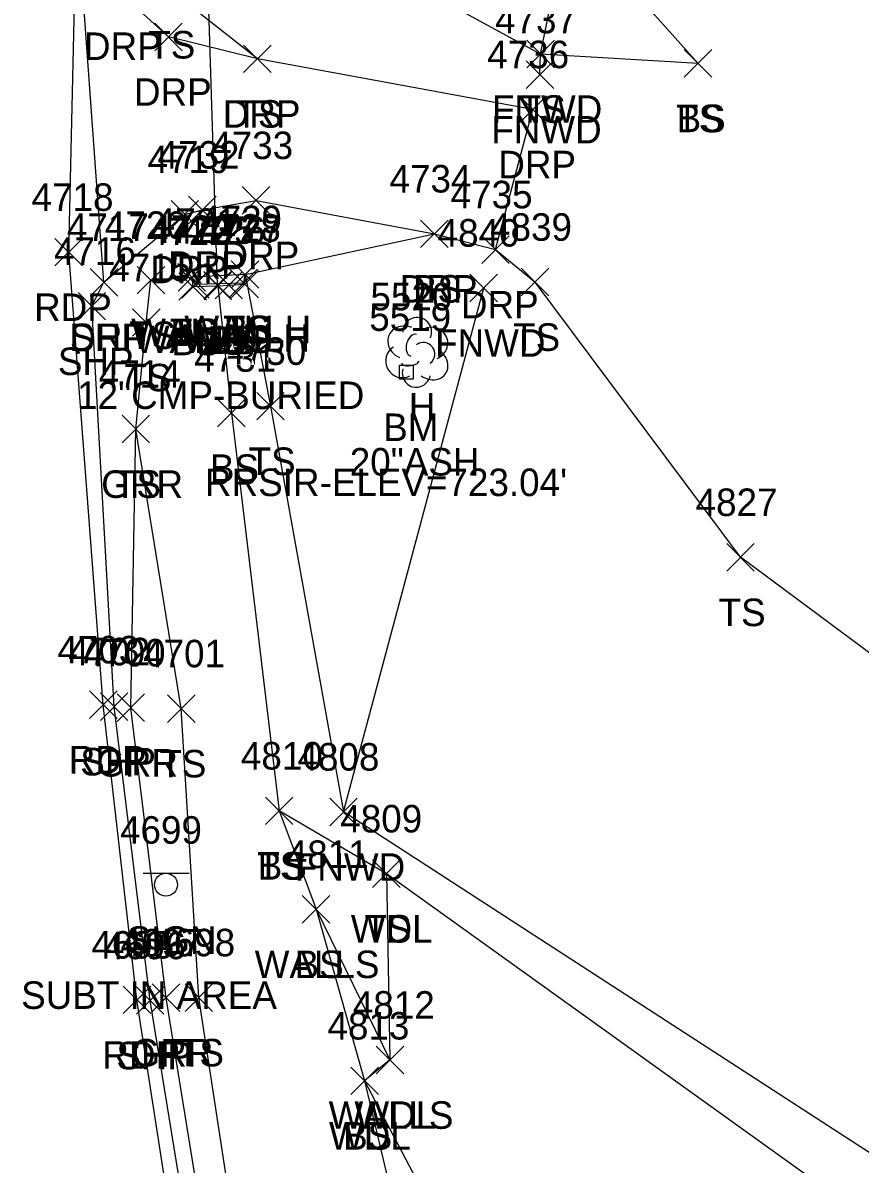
# Model space of a CAD drawing. Extents: x 1601151 to 1602912, y 499508 to 501770.
# Drawn here: x 1601465.9 to 1601526.7, y 501166.3 to 501249.2 of the extents above; entities that cross this region are included whole.
import ezdxf

# ---------------------------------------------------------------- set-up
doc = ezdxf.new("R2010")
doc.units = 0
for name, color, linetype in [('C_A', 7, 'Continuous'), ('C_C', 7, 'Continuous'), ('C_I', 7, 'Continuous'), ('CPBM', 7, 'Continuous'), ('D_A', 7, 'Continuous'), ('D_C', 7, 'Continuous'), ('D_I', 7, 'Continuous'), ('D_TIC', 7, 'Continuous'), ('DCP', 7, 'Continuous'), ('DHW', 7, 'Continuous'), ('L_A', 7, 'Continuous'), ('L_C', 7, 'Continuous'), ('L_I', 7, 'Continuous'), ('L_TIC', 7, 'Continuous'), ('LAWA', 7, 'Continuous'), ('LELB', 7, 'Continuous'), ('LFNC', 7, 'Continuous'), ('LTD', 7, 'Continuous'), ('LWS', 7, 'Continuous'), ('P_A', 7, 'Continuous'), ('P_I', 7, 'Continuous'), ('P_TIC', 7, 'Continuous'), ('PET', 7, 'Continuous'), ('PSP', 7, 'Continuous'), ('R_A', 7, 'Continuous'), ('R_I', 7, 'Continuous'), ('R_TIC', 7, 'Continuous'), ('RDP', 7, 'Continuous'), ('RGR', 7, 'Continuous'), ('S_A', 7, 'Continuous'), ('S_C', 7, 'Continuous'), ('S_I', 7, 'Continuous'), ('SSGN', 7, 'Continuous')]:
    doc.layers.add(name, color=color, linetype=linetype)

msp = doc.modelspace()

# ---------------------------------------------------------------- linework, layer by layer
at = {"layer": 'CPBM'}
for p, q in [((1601493.23, 501223.31), (1601493.23, 501224.31)), ((1601493.23, 501224.31), (1601494.23, 501224.31)), ((1601493.733, 501223.811), (1601493.733, 501223.811)), ((1601493.733, 501223.811), (1601493.733, 501223.811)), ((1601494.23, 501224.31), (1601494.23, 501223.31)), ((1601494.23, 501223.31), (1601493.23, 501223.31))]:
    msp.add_line(p, q, dxfattribs=at)
at = {"layer": 'D_TIC'}
for points in [[(1601481.012, 501229.91), (1601483.012, 501231.91)], [(1601483.012, 501229.91), (1601481.012, 501231.91)], [(1601477.146, 501229.707), (1601479.146, 501231.707)], [(1601479.146, 501229.707), (1601477.146, 501231.707)], [(1601477.41, 501229.196), (1601479.41, 501231.196)], [(1601479.41, 501229.196), (1601477.41, 501231.196)], [(1601479.011, 501229.137), (1601481.011, 501231.137)], [(1601481.011, 501229.137), (1601479.011, 501231.137)], [(1601480.918, 501229.293), (1601482.918, 501231.293)], [(1601482.918, 501229.293), (1601480.918, 501231.293)]]:
    msp.add_lwpolyline(points, dxfattribs=at)
at = {"layer": 'DCP'}
msp.add_lwpolyline([(1601480.011, 501230.137), (1601479.12, 501258.606)], dxfattribs=at)
at = {"layer": 'DHW'}
msp.add_lwpolyline([(1601478.146, 501230.707), (1601478.41, 501230.196), (1601481.918, 501230.293), (1601482.012, 501230.91), (1601478.146, 501230.707)], dxfattribs=at)
at = {"layer": 'L_TIC'}
for points in [[(1601502.48, 501245.927), (1601504.48, 501247.927)], [(1601504.48, 501245.927), (1601502.48, 501247.927)], [(1601502.48, 501245.927), (1601504.48, 501247.927)], [(1601504.48, 501245.927), (1601502.48, 501247.927)], [(1601481.904, 501245.572), (1601483.904, 501247.572)], [(1601483.904, 501245.572), (1601481.904, 501247.572)], [(1601513.919, 501245.246), (1601515.919, 501247.246)], [(1601515.919, 501245.246), (1601513.919, 501247.246)], [(1601513.919, 501245.246), (1601515.919, 501247.246)], [(1601515.919, 501245.246), (1601513.919, 501247.246)], [(1601502.433, 501244.429), (1601504.433, 501246.429)], [(1601504.433, 501244.429), (1601502.433, 501246.429)], [(1601494.765, 501232.865), (1601496.765, 501234.865)], [(1601496.765, 501232.865), (1601494.765, 501234.865)], [(1601481.012, 501229.91), (1601483.012, 501231.91)], [(1601483.012, 501229.91), (1601481.012, 501231.91)], [(1601481.012, 501229.91), (1601483.012, 501231.91)], [(1601483.012, 501229.91), (1601481.012, 501231.91)], [(1601474.177, 501229.496), (1601476.177, 501231.496)], [(1601476.177, 501229.496), (1601474.177, 501231.496)], [(1601477.146, 501229.707), (1601479.146, 501231.707)], [(1601479.146, 501229.707), (1601477.146, 501231.707)], [(1601477.146, 501229.707), (1601479.146, 501231.707)], [(1601479.146, 501229.707), (1601477.146, 501231.707)], [(1601479.037, 501229.075), (1601481.037, 501231.075)], [(1601481.037, 501229.075), (1601479.037, 501231.075)], [(1601479.037, 501229.075), (1601481.037, 501231.075)], [(1601481.037, 501229.075), (1601479.037, 501231.075)], [(1601479.837, 501229.133), (1601481.837, 501231.133)], [(1601481.837, 501229.133), (1601479.837, 501231.133)], [(1601480.999, 501229.207), (1601482.999, 501231.207)], [(1601482.999, 501229.207), (1601480.999, 501231.207)], [(1601502.076, 501229.359), (1601504.076, 501231.359)], [(1601504.076, 501229.359), (1601502.076, 501231.359)], [(1601477.207, 501229.04), (1601479.207, 501231.04)], [(1601479.207, 501229.04), (1601477.207, 501231.04)], [(1601498.348, 501228.934), (1601500.348, 501230.934)], [(1601500.348, 501228.934), (1601498.348, 501230.934)], [(1601473.84, 501226.419), (1601475.84, 501228.419)], [(1601475.84, 501226.419), (1601473.84, 501228.419)], [(1601482.857, 501220.341), (1601484.857, 501222.341)], [(1601484.857, 501220.341), (1601482.857, 501222.341)], [(1601480.019, 501219.841), (1601482.019, 501221.841)], [(1601482.019, 501219.841), (1601480.019, 501221.841)], [(1601473.075, 501218.68), (1601475.075, 501220.68)], [(1601475.075, 501218.68), (1601473.075, 501220.68)], [(1601516.999, 501209.362), (1601518.999, 501211.362)], [(1601518.999, 501209.362), (1601516.999, 501211.362)], [(1601476.376, 501198.371), (1601478.376, 501200.371)], [(1601478.376, 501198.371), (1601476.376, 501200.371)], [(1601483.49, 501190.946), (1601485.49, 501192.946)], [(1601485.49, 501190.946), (1601483.49, 501192.946)], [(1601483.49, 501190.946), (1601485.49, 501192.946)], [(1601485.49, 501190.946), (1601483.49, 501192.946)], [(1601488.16, 501190.866), (1601490.16, 501192.866)], [(1601490.16, 501190.866), (1601488.16, 501192.866)], [(1601491.276, 501186.375), (1601493.276, 501188.375)], [(1601493.276, 501186.375), (1601491.276, 501188.375)], [(1601491.276, 501186.375), (1601493.276, 501188.375)], [(1601493.276, 501186.375), (1601491.276, 501188.375)], [(1601486.168, 501183.794), (1601488.168, 501185.794)], [(1601488.168, 501183.794), (1601486.168, 501185.794)], [(1601486.168, 501183.794), (1601488.168, 501185.794)], [(1601488.168, 501183.794), (1601486.168, 501185.794)], [(1601477.65, 501177.376), (1601479.65, 501179.376)], [(1601479.65, 501177.376), (1601477.65, 501179.376)], [(1601491.537, 501172.845), (1601493.537, 501174.845)], [(1601493.537, 501172.845), (1601491.537, 501174.845)], [(1601491.537, 501172.845), (1601493.537, 501174.845)], [(1601493.537, 501172.845), (1601491.537, 501174.845)], [(1601489.694, 501171.332), (1601491.694, 501173.332)], [(1601491.694, 501171.332), (1601489.694, 501173.332)], [(1601489.694, 501171.332), (1601491.694, 501173.332)], [(1601491.694, 501171.332), (1601489.694, 501173.332)]]:
    msp.add_lwpolyline(points, dxfattribs=at)
at = {"layer": 'LAWA'}
msp.add_lwpolyline([(1601618.164, 501105.861), (1601588.542, 501115.646), (1601565.4, 501138.093), (1601542.306, 501150.134), (1601528.872, 501161.109), (1601492.276, 501187.375), (1601492.537, 501173.845), (1601490.694, 501172.332), (1601496.325, 501148.536)], dxfattribs=at)
at = {"layer": 'LELB'}
for points in [[(1601514.919, 501246.246), (1601505.474, 501256.797), (1601486.015, 501263.271), (1601485.756, 501300.208), (1601487.942, 501339.809), (1601496.982, 501373.173)], [(1601482.904, 501246.572), (1601476.571, 501251.598), (1601473.853, 501259.286)], [(1601514.919, 501246.246), (1601503.48, 501246.927), (1601485.983, 501256.464), (1601481.191, 501258.282)], [(1601478.146, 501230.707), (1601478.207, 501230.04), (1601480.037, 501230.075), (1601480.837, 501230.133), (1601481.999, 501230.207), (1601482.012, 501230.91), (1601495.765, 501233.865)], [(1601500.206, 501232.716), (1601503.076, 501230.359)], [(1601550.273, 500878.876), (1601544.145, 500896.684), (1601533.206, 500944.653), (1601522.547, 500986.897), (1601510.781, 501028.923), (1601500.628, 501071.758), (1601491.578, 501108.108), (1601483.828, 501144.538), (1601478.65, 501178.376), (1601477.376, 501199.371), (1601474.075, 501219.68), (1601474.84, 501227.419), (1601475.177, 501230.496), (1601478.146, 501230.707)], [(1601482.012, 501230.91), (1601483.857, 501221.341)], [(1601639.017, 501157.644), (1601611.095, 501171.108), (1601584.804, 501178.755), (1601542.463, 501192.221), (1601517.999, 501210.362), (1601503.076, 501230.359)], [(1601480.037, 501230.075), (1601481.019, 501220.841), (1601484.49, 501191.946), (1601487.168, 501184.794), (1601490.694, 501172.332), (1601502.321, 501150.223), (1601523.309, 501131.225), (1601544.426, 501107.876), (1601586.902, 501067.79), (1601615.046, 501058.933)], [(1601483.857, 501221.341), (1601489.16, 501191.866)], [(1601492.276, 501187.375), (1601484.49, 501191.946)]]:
    msp.add_lwpolyline(points, dxfattribs=at)
at = {"layer": 'LFNC'}
for points in [[(1601503.433, 501245.429), (1601503.48, 501246.927), (1601505.474, 501256.797), (1601514.287, 501293.696), (1601516.13, 501305.057)], [(1601618.917, 501107.15), (1601588.692, 501127.511), (1601566.226, 501142.234), (1601531.272, 501164.593), (1601489.16, 501191.866), (1601499.348, 501229.934)]]:
    msp.add_lwpolyline(points, dxfattribs=at)
at = {"layer": 'LTD'}
msp.add_line((1601494.469, 501225.304), (1601494.469, 501225.304), dxfattribs=at)
msp.add_line((1601494.469, 501225.304), (1601494.469, 501225.304), dxfattribs=at)
msp.add_arc((1601494.515, 501226.738), 1.047, 335.52715, 180.95627, dxfattribs=at)
for centre, major_axis, ratio, start_param, end_param in [((1601493.677, 501225.97), (1.21, -0.512), 0.895232, 1.570796, 4.712389), ((1601495.51, 501225.887), (-1.141, -0.483), 0.949671, 1.570796, 4.712389), ((1601494.26, 501225.762), (-0.208, -0.792), 0.645439, 3.141593, 6.283185), ((1601493.385, 501224.595), (0.584, -1.042), 0.959034, 3.141593, 6.283185), ((1601494.969, 501225.137), (-0.5, 0.667), 0.989748, 3.141593, 6.283185), ((1601495.469, 501224.47), (-1.09, 0.792), 0.841452, 1.570796, 4.712389), ((1601494.01, 501224.554), (-0.625, -0.083), 0.423636, 0, 3.141593), ((1601494.469, 501223.804), (0.265, 1.061), 0.942809, 1.570796, 4.712389)]:
    msp.add_ellipse(centre, major_axis=major_axis, ratio=ratio, start_param=start_param, end_param=end_param, dxfattribs=at)
at = {"layer": 'LWS'}
msp.add_lwpolyline([(1601487.168, 501184.794), (1601492.537, 501173.845)], dxfattribs=at)
at = {"layer": 'P_TIC'}
for points in [[(1601468.2, 501231.531), (1601470.2, 501233.531)], [(1601470.2, 501231.531), (1601468.2, 501233.531)], [(1601470.762, 501229.344), (1601472.762, 501231.344)], [(1601472.762, 501229.344), (1601470.762, 501231.344)], [(1601469.881, 501227.604), (1601471.881, 501229.604)], [(1601471.881, 501227.604), (1601469.881, 501229.604)], [(1601470.716, 501198.657), (1601472.716, 501200.657)], [(1601472.716, 501198.657), (1601470.716, 501200.657)], [(1601471.506, 501198.517), (1601473.506, 501200.517)], [(1601473.506, 501198.517), (1601471.506, 501200.517)], [(1601473.157, 501177.212), (1601475.157, 501179.212)], [(1601475.157, 501177.212), (1601473.157, 501179.212)], [(1601474.123, 501177.167), (1601476.123, 501179.167)], [(1601476.123, 501177.167), (1601474.123, 501179.167)]]:
    msp.add_lwpolyline(points, dxfattribs=at)
at = {"layer": 'PET'}
msp.add_lwpolyline([(1601544.222, 500876.259), (1601539.18, 500895.586), (1601526.946, 500943.367), (1601516.322, 500985.835), (1601505.443, 501027.918), (1601495.097, 501070.934), (1601486.999, 501107.137), (1601479.481, 501143.907), (1601474.157, 501178.212), (1601471.716, 501199.657), (1601469.2, 501232.531), (1601470.852, 501304.368), (1601475.757, 501342.264), (1601481.23, 501372.738), (1601489.711, 501419.604), (1601498.833, 501463.236), (1601509.832, 501514.715), (1601518.287, 501552.564), (1601529.192, 501602.718), (1601530.089, 501606.928), (1601533.566, 501622.361), (1601544.656, 501669.882)], dxfattribs=at)
at = {"layer": 'PSP'}
msp.add_lwpolyline([(1601528.905, 500943.602), (1601517.981, 500986.134), (1601507.436, 501028.318), (1601496.624, 501071.208), (1601488.243, 501107.282), (1601480.675, 501144.124), (1601475.123, 501178.167), (1601472.506, 501199.517), (1601470.881, 501228.604), (1601471.762, 501230.344), (1601469.82, 501257.161), (1601471.596, 501304.231), (1601477.349, 501341.751), (1601482.297, 501372.174), (1601491.335, 501419.441), (1601500.561, 501462.845), (1601511.149, 501514.361), (1601520.065, 501552.198), (1601531.25, 501603.068), (1601534.571, 501619.483), (1601535.229, 501620.043), (1601536.149, 501623.424), (1601535.022, 501624.102), (1601546.219, 501669.664)], dxfattribs=at)
at = {"layer": 'R_TIC'}
for points in [[(1601475.453, 501247.166), (1601477.453, 501249.166)], [(1601477.453, 501247.166), (1601475.453, 501249.166)], [(1601481.904, 501245.572), (1601483.904, 501247.572)], [(1601483.904, 501245.572), (1601481.904, 501247.572)], [(1601501.918, 501241.897), (1601503.918, 501243.897)], [(1601503.918, 501241.897), (1601501.918, 501243.897)], [(1601481.813, 501235.293), (1601483.813, 501237.293)], [(1601483.813, 501235.293), (1601481.813, 501237.293)], [(1601476.633, 501234.273), (1601478.633, 501236.273)], [(1601478.633, 501234.273), (1601476.633, 501236.273)], [(1601477.914, 501234.599), (1601479.914, 501236.599)], [(1601479.914, 501234.599), (1601477.914, 501236.599)], [(1601494.765, 501232.865), (1601496.765, 501234.865)], [(1601496.765, 501232.865), (1601494.765, 501234.865)], [(1601499.206, 501231.716), (1601501.206, 501233.716)], [(1601501.206, 501231.716), (1601499.206, 501233.716)], [(1601470.762, 501229.344), (1601472.762, 501231.344)], [(1601472.762, 501229.344), (1601470.762, 501231.344)], [(1601473.075, 501218.68), (1601475.075, 501220.68)], [(1601475.075, 501218.68), (1601473.075, 501220.68)], [(1601472.71, 501198.437), (1601474.71, 501200.437)], [(1601474.71, 501198.437), (1601472.71, 501200.437)], [(1601475.276, 501177.369), (1601477.276, 501179.369)], [(1601477.276, 501177.369), (1601475.276, 501179.369)]]:
    msp.add_lwpolyline(points, dxfattribs=at)
at = {"layer": 'RDP'}
msp.add_lwpolyline([(1601471.762, 501230.344), (1601477.633, 501235.273), (1601478.914, 501235.599), (1601482.813, 501236.293), (1601495.765, 501233.865), (1601500.206, 501232.716), (1601502.918, 501242.897), (1601482.904, 501246.572), (1601476.453, 501248.166), (1601472.823, 501251.493), (1601469.82, 501257.161)], dxfattribs=at)
at = {"layer": 'RGR'}
msp.add_lwpolyline([(1601542.078, 500896.217), (1601529.827, 500944.353), (1601519.229, 500986.393), (1601508.51, 501028.956), (1601497.809, 501071.106), (1601488.919, 501107.458), (1601481.799, 501144.254), (1601476.276, 501178.369), (1601473.71, 501199.437), (1601474.075, 501219.68)], dxfattribs=at)
at = {"layer": 'SSGN'}
for p, q in [((1601474.616, 501187.41), (1601477.95, 501187.41)), ((1601476.263, 501186.577), (1601476.263, 501186.577))]:
    msp.add_line(p, q, dxfattribs=at)
msp.add_circle((1601476.263, 501186.577), 0.833, dxfattribs=at)

# ---------------------------------------------------------------- texts
at = {"layer": 'C_A'}
msp.add_text('BM', height=2, dxfattribs=at).set_placement((1601492.048, 501218.811))
at = {"layer": 'C_C'}
msp.add_text("RRSIR-ELEV=723.04'", height=2, dxfattribs=at).set_placement((1601479.103, 501214.811))
at = {"layer": 'C_I'}
msp.add_text('5519', height=2, dxfattribs=at).set_placement((1601491.032, 501226.811))
at = {"layer": 'D_A'}
for s, p in [('WALLH', (1601477.603, 501225.91)), ('WALLH', (1601473.737, 501225.707)), ('WALLH', (1601474, 501225.196)), ('WALLH', (1601477.508, 501225.293)), ('P', (1601479.389, 501225.137))]:
    msp.add_text(s, height=2, dxfattribs=at).set_placement(p)
at = {"layer": 'D_C'}
msp.add_text('12"CMP-BURIED', height=2, dxfattribs=at).set_placement((1601469.814, 501221.137))
at = {"layer": 'D_I'}
for s, p in [('4723', (1601475.15, 501233.196)), ('4721', (1601475.453, 501233.707)), ('4728', (1601478.658, 501233.293)), ('4729', (1601478.744, 501233.91)), ('4725', (1601476.751, 501233.137))]:
    msp.add_text(s, height=2, dxfattribs=at).set_placement(p)
at = {"layer": 'L_A'}
for s, p in [('TS', (1601474.98, 501246.598)), ('TS', (1601481.314, 501241.572)), ('FNWD', (1601499.944, 501241.927)), ('TS', (1601501.889, 501241.927)), ('TS', (1601513.328, 501241.246)), ('BS', (1601513.359, 501241.246)), ('FNWD', (1601499.897, 501240.429)), ('BS', (1601494.206, 501228.865)), ('TS', (1601480.421, 501225.91)), ('BS', (1601480.453, 501225.91)), ('TS', (1601473.586, 501225.496)), ('TS', (1601476.556, 501225.707)), ('BS', (1601476.587, 501225.707)), ('BS', (1601476.648, 501225.04)), ('BS', (1601478.478, 501225.075)), ('BS', (1601478.478, 501225.075)), ('BS', (1601479.278, 501225.133)), ('BS', (1601480.44, 501225.207)), ('FNWD', (1601495.813, 501224.934)), ('TS', (1601501.486, 501225.359)), ('TS', (1601473.249, 501222.419)), ('H', (1601493.902, 501220.304)), ('BS', (1601479.46, 501215.841)), ('TS', (1601482.266, 501216.341)), ('TS', (1601472.485, 501214.68)), ('TS', (1601516.409, 501205.362)), ('TS', (1601475.786, 501194.371)), ('TS', (1601482.899, 501186.946)), ('BS', (1601482.931, 501186.946)), ('FNWD', (1601485.625, 501186.866)), ('WDL', (1601489.693, 501182.375)), ('TS', (1601490.685, 501182.375)), ('WALLS', (1601482.711, 501179.794)), ('BS', (1601485.609, 501179.794)), ('TS', (1601477.059, 501173.376)), ('WALLS', (1601488.08, 501168.845)), ('WDL', (1601489.954, 501168.845)), ('WDL', (1601488.111, 501167.332)), ('BS', (1601489.135, 501167.332))]:
    msp.add_text(s, height=2, dxfattribs=at).set_placement(p)
at = {"layer": 'L_C'}
msp.add_text('20"ASH', height=2, dxfattribs=at).set_placement((1601489.618, 501216.304))
at = {"layer": 'L_I'}
for s, p in [('4737', (1601500.173, 501248.429)), ('4734', (1601492.505, 501236.865)), ('4720', (1601471.83, 501233.496)), ('4721', (1601475.453, 501233.707)), ('4721', (1601475.453, 501233.707)), ('4727', (1601478.739, 501233.207)), ('4729', (1601478.744, 501233.91)), ('4729', (1601478.744, 501233.91)), ('4839', (1601499.809, 501233.359)), ('4722', (1601474.948, 501233.04)), ('4724', (1601476.777, 501233.075)), ('4724', (1601476.777, 501233.075)), ('4726', (1601477.522, 501233.133)), ('4840', (1601496.002, 501232.934)), ('4715', (1601472.147, 501230.419)), ('5520', (1601491.122, 501228.304)), ('4730', (1601480.51, 501224.341)), ('4731', (1601478.326, 501223.841)), ('4714', (1601471.383, 501222.68)), ('4827', (1601514.74, 501213.362)), ('4701', (1601474.605, 501202.371)), ('4810', (1601481.71, 501194.946)), ('4810', (1601481.71, 501194.946)), ('4808', (1601485.822, 501194.866)), ('4809', (1601488.929, 501190.375)), ('4809', (1601488.929, 501190.375)), ('4811', (1601485.042, 501187.794)), ('4811', (1601485.042, 501187.794)), ('4698', (1601475.343, 501181.376)), ('4812', (1601489.844, 501176.845)), ('4812', (1601489.844, 501176.845)), ('4813', (1601488.001, 501175.332)), ('4813', (1601488.001, 501175.332))]:
    msp.add_text(s, height=2, dxfattribs=at).set_placement(p)
at = {"layer": 'P_A'}
for s, p in [('RDP', (1601466.688, 501227.531)), ('SHP', (1601469.298, 501225.344)), ('SHP', (1601468.416, 501223.604)), ('RDP', (1601469.204, 501194.657)), ('SHP', (1601470.041, 501194.517)), ('RDP', (1601471.646, 501173.212)), ('SHP', (1601472.659, 501173.167))]:
    msp.add_text(s, height=2, dxfattribs=at).set_placement(p)
at = {"layer": 'P_I'}
for s, p in [('4718', (1601466.507, 501235.531)), ('4717', (1601469.07, 501233.344)), ('4716', (1601468.133, 501231.604)), ('4703', (1601468.378, 501202.657)), ('4702', (1601469.167, 501202.517)), ('4695', (1601470.85, 501181.212)), ('4696', (1601471.761, 501181.167))]:
    msp.add_text(s, height=2, dxfattribs=at).set_placement(p)
at = {"layer": 'R_A'}
for s, p in [('DRP', (1601470.311, 501246.493)), ('DRP', (1601473.942, 501243.166)), ('DRP', (1601480.392, 501241.572)), ('DRP', (1601500.406, 501237.897)), ('DRP', (1601480.301, 501231.293)), ('DRP', (1601475.121, 501230.273)), ('DRP', (1601476.403, 501230.599)), ('DRP', (1601493.253, 501228.865)), ('DRP', (1601497.694, 501227.716)), ('DRP', (1601469.251, 501225.344)), ('GRR', (1601471.563, 501214.68)), ('GRR', (1601471.198, 501194.437)), ('GRR', (1601473.765, 501173.369))]:
    msp.add_text(s, height=2, dxfattribs=at).set_placement(p)
at = {"layer": 'R_I'}
for s, p in [('4736', (1601499.603, 501245.897)), ('4733', (1601479.553, 501239.293)), ('4719', (1601474.933, 501238.273)), ('4732', (1601475.655, 501238.599)), ('4734', (1601492.505, 501236.865)), ('4735', (1601496.946, 501235.716)), ('4717', (1601469.07, 501233.344)), ('4714', (1601471.383, 501222.68)), ('4700', (1601470.285, 501202.437)), ('4697', (1601472.969, 501181.369))]:
    msp.add_text(s, height=2, dxfattribs=at).set_placement(p)
at = {"layer": 'S_A'}
msp.add_text('SIGN', height=2, dxfattribs=at).set_placement((1601473.401, 501181.557))
at = {"layer": 'S_C'}
msp.add_text('SUBT IN AREA', height=2, dxfattribs=at).set_placement((1601465.748, 501177.557))
at = {"layer": 'S_I'}
msp.add_text('4699', height=2, dxfattribs=at).set_placement((1601472.929, 501189.557))

doc.saveas('drawing.dxf')
